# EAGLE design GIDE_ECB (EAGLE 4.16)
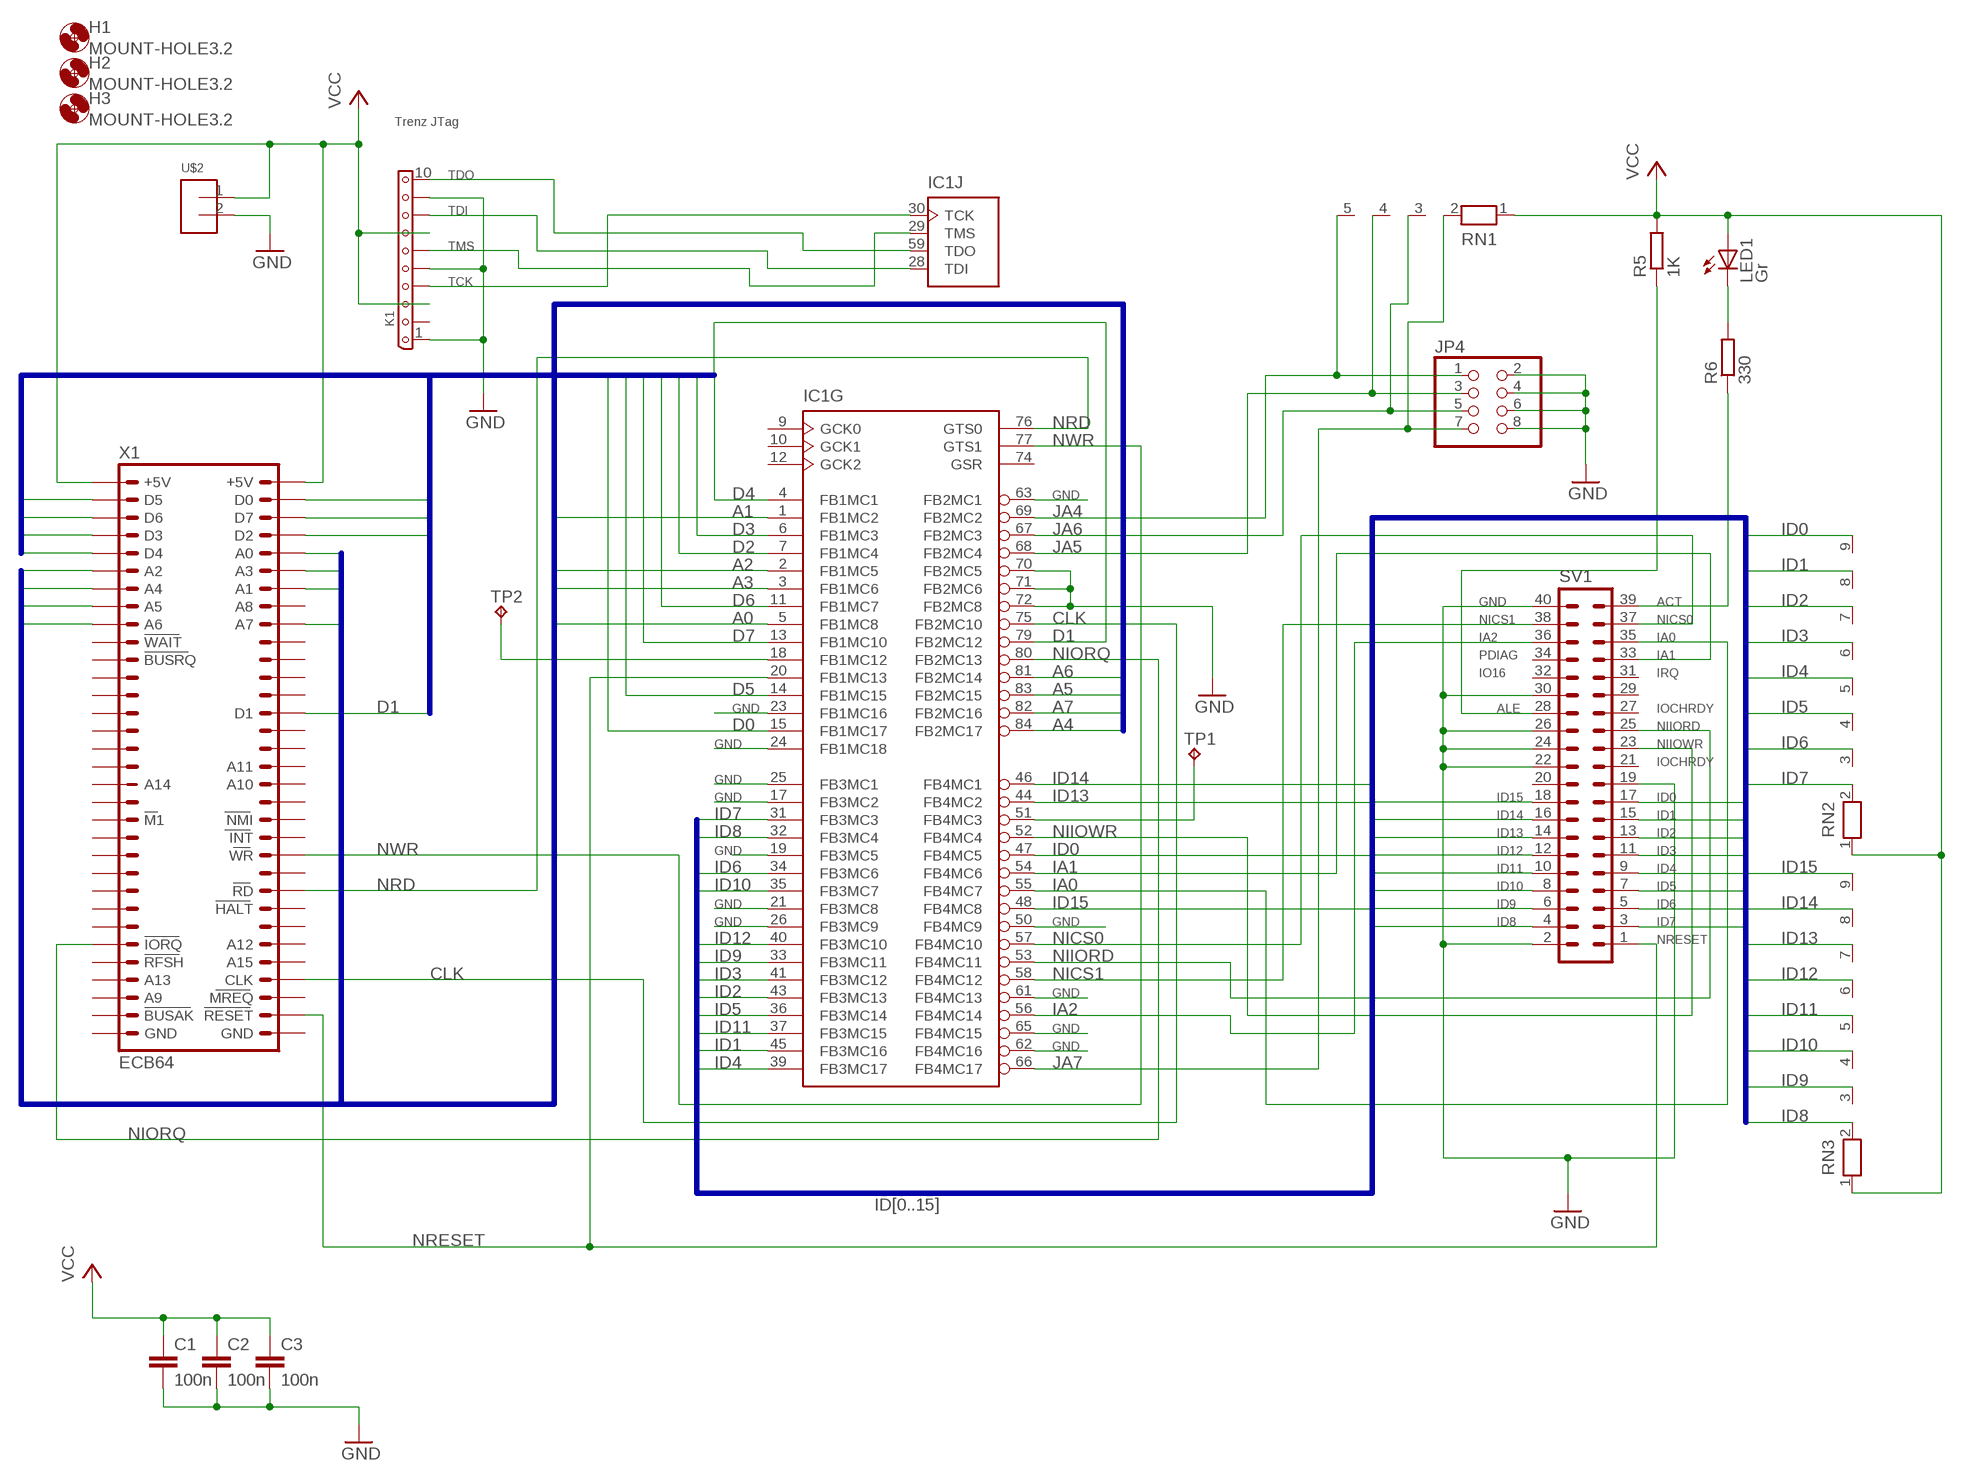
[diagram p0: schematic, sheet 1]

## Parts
C1  100n  C-EU025-024X044  [C025-024X044]
C2  100n  C-EU025-024X044  [C025-024X044]
C3  100n  C-EU025-024X044  [C025-024X044]
H1  MOUNT-HOLE3.2  [3,2]
H2  MOUNT-HOLE3.2  [3,2]
H3  MOUNT-HOLE3.2  [3,2]
IC1  XC9572PC84  [PLCC-S84]
JP4  PINHD-2X4  [2X04]
K1  PFOSTENSTECKER-10  [PFOSTENSTECKER-10]
LED1  Gr  LED3MM  [LED3MM]
R5  1K  R-EU_0207/10  [0207/10]
R6  330  R-EU_0204/7  [0204/7]
RN1  RN04  [RN-5]
RN2  RN08  [RN-9]
RN3  RN08  [RN-9]
SV1  ML40  [ML40]
TP1  TPPAD1-13  [P1-13]
TP2  TPPAD1-13  [P1-13]
U$2  PS25/2G  [PS25-2G]
X1  ECB64  [ML64ECB]

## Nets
A0: IC1.5(G:FB1MC8) X1.A0
A1: IC1.1(G:FB1MC2) X1.A1
A2: IC1.2(G:FB1MC5) X1.A2
A3: IC1.3(G:FB1MC6) X1.A3
A4: IC1.84(G:FB2MC17) X1.A4
A5: IC1.83(G:FB2MC15) X1.A5
A6: IC1.81(G:FB2MC14) X1.A6
A7: IC1.82(G:FB2MC16) X1.A7
ACT: R6.1 SV1.39
ALE: R5.1 SV1.28
CLK: IC1.75(G:FB2MC10) X1.CLK
D0: IC1.15(G:FB1MC17) X1.D0
D1: IC1.79(G:FB2MC12) X1.D1
D2: IC1.7(G:FB1MC4) X1.D2
D3: IC1.6(G:FB1MC3) X1.D3
D4: IC1.4(G:FB1MC1) X1.D4
D5: IC1.14(G:FB1MC15) X1.D5
D6: IC1.11(G:FB1MC7) X1.D6
D7: IC1.13(G:FB1MC10) X1.D7
GND: C1.2 C2.2 C3.2 IC1.17(G:FB3MC2) IC1.19(G:FB3MC5) IC1.21(G:FB3MC8) IC1.23(G:FB1MC16) IC1.24(G:FB1MC18) IC1.25(G:FB3MC1) IC1.26(G:FB3MC9) IC1.50(G:FB4MC9) IC1.61(G:FB4MC13) IC1.62(G:FB4MC16) IC1.63(G:FB2MC1) IC1.65(G:FB4MC15) IC1.70(G:FB2MC5) IC1.71(G:FB2MC6) IC1.72(G:FB2MC8) JP4.2 JP4.4 JP4.6 JP4.8 K1.1 K1.5 K1.9 SV1.2 SV1.19 SV1.22 SV1.24 SV1.26 SV1.30 SV1.40 U$2.2
IA0: IC1.55(G:FB4MC7) SV1.35
IA1: IC1.54(G:FB4MC6) SV1.33
IA2: IC1.56(G:FB4MC14) SV1.36
ID0: IC1.47(G:FB4MC5) RN2.9 SV1.17
ID1: IC1.45(G:FB3MC16) RN2.8 SV1.15
ID2: IC1.43(G:FB3MC13) RN2.7 SV1.13
ID3: IC1.41(G:FB3MC12) RN2.6 SV1.11
ID4: IC1.39(G:FB3MC17) RN2.5 SV1.9
ID5: IC1.36(G:FB3MC14) RN2.4 SV1.7
ID6: IC1.34(G:FB3MC6) RN2.3 SV1.5
ID7: IC1.31(G:FB3MC3) RN2.2 SV1.3
ID8: IC1.32(G:FB3MC4) RN3.2 SV1.4
ID9: IC1.33(G:FB3MC11) RN3.3 SV1.6
ID10: IC1.35(G:FB3MC7) RN3.4 SV1.8
ID11: IC1.37(G:FB3MC15) RN3.5 SV1.10
ID12: IC1.40(G:FB3MC10) RN3.6 SV1.12
ID13: IC1.44(G:FB4MC2) RN3.7 SV1.14
ID14: IC1.46(G:FB4MC1) RN3.8 SV1.16
ID15: IC1.48(G:FB4MC8) RN3.9 SV1.18
JA4: IC1.69(G:FB2MC2) JP4.1 RN1.5
JA5: IC1.68(G:FB2MC4) JP4.3 RN1.4
JA6: IC1.67(G:FB2MC3) JP4.5 RN1.3
JA7: IC1.66(G:FB4MC17) JP4.7 RN1.2
N$1: IC1.51(G:FB4MC3) TP1.1(TP)
N$2: IC1.18(G:FB1MC12) TP2.1(TP)
N$16: LED1.K(C) R6.2
NICS0: IC1.57(G:FB4MC10) SV1.37
NICS1: IC1.58(G:FB4MC12) SV1.38
NIIORD: IC1.53(G:FB4MC11) SV1.25
NIIOWR: IC1.52(G:FB4MC4) SV1.23
NIORQ: IC1.80(G:FB2MC13) X1.IORQ
NRD: IC1.76(G:GTS0) X1.RD
NRESET: IC1.20(G:FB1MC13) SV1.1 X1.RESET
NWR: IC1.77(G:GTS1) X1.WR
TCK: IC1.30(J:TCK) K1.4
TDI: IC1.28(J:TDI) K1.8
TDO: IC1.59(J:TDO) K1.10
TMS: IC1.29(J:TMS) K1.6
VCC: C1.1 C2.1 C3.1 K1.3 K1.7 LED1.A R5.2 RN1.1 RN2.1 RN3.1 U$2.1 X1.+5V X1.+5V@1(+5V)
Unconnected: IC1.9(G:GCK0) IC1.10(G:GCK1) IC1.12(G:GCK2) IC1.74(G:GSR) K1.2 SV1.20 SV1.21 SV1.27 SV1.29 SV1.31 SV1.32 SV1.34 X1.10C X1.11C X1.12A X1.12C X1.13A X1.13C X1.14A X1.15A X1.15C X1.16A X1.16C X1.17A X1.19A X1.19C X1.21A X1.22A X1.23A X1.23C X1.24A X1.25A X1.26A X1.26C X1.A8 X1.A9 X1.A10 X1.A11 X1.A12 X1.A13 X1.A14 X1.A15 X1.BUSAK X1.BUSRQ X1.HALT X1.INT X1.M1 X1.MREQ X1.NMI X1.RFSH X1.WAIT

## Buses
ID[0..15]
D[0..7]
A[0..7]

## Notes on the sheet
- Trenz JTag
- PDIAG
- IO16 | IRQ
- IOCHRDY
- IOCHRDY

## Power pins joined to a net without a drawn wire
GND: IC1.8(P:GND) IC1.16(P:GND) IC1.27(P:GND) IC1.42(P:GND) IC1.49(P:GND) IC1.60(P:GND) X1.GND X1.GND@1(GND)
VCC: IC1.22(P:VCC) IC1.38(P:VCC) IC1.64(P:VCC) IC1.73(P:VCC) IC1.78(P:VCC)

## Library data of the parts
C1-C3 = rcl:C-EU: CAPACITOR, European symbol
H1-H3 = holes:MOUNT-HOLE: MOUNTING HOLE with drill center marker
IC1 = XILINX:XC9572PC84
JP4 = pinhead:PINHD-2X4: PIN HEADER
K1 = ad:PFOSTENSTECKER-10
LED1 = led:LED: LED
R5 R6 = rcl:R-EU_: RESISTOR, European symbol
RN1 = resistor-net:RN04: RESISTOR NETWORK
RN2 RN3 = resistor-net:RN08: RESISTOR NETWORK
SV1 = con-harting-ml:ML40: HARTING
TP1 TP2 = testpad:TP
U$2 = ad:PS25/2G: Reichelt PS 25/2G
X1 = eigene:ECB64: CONNECTOR male, 64 pins, block, type C, rows AC, grid 5.08 mm

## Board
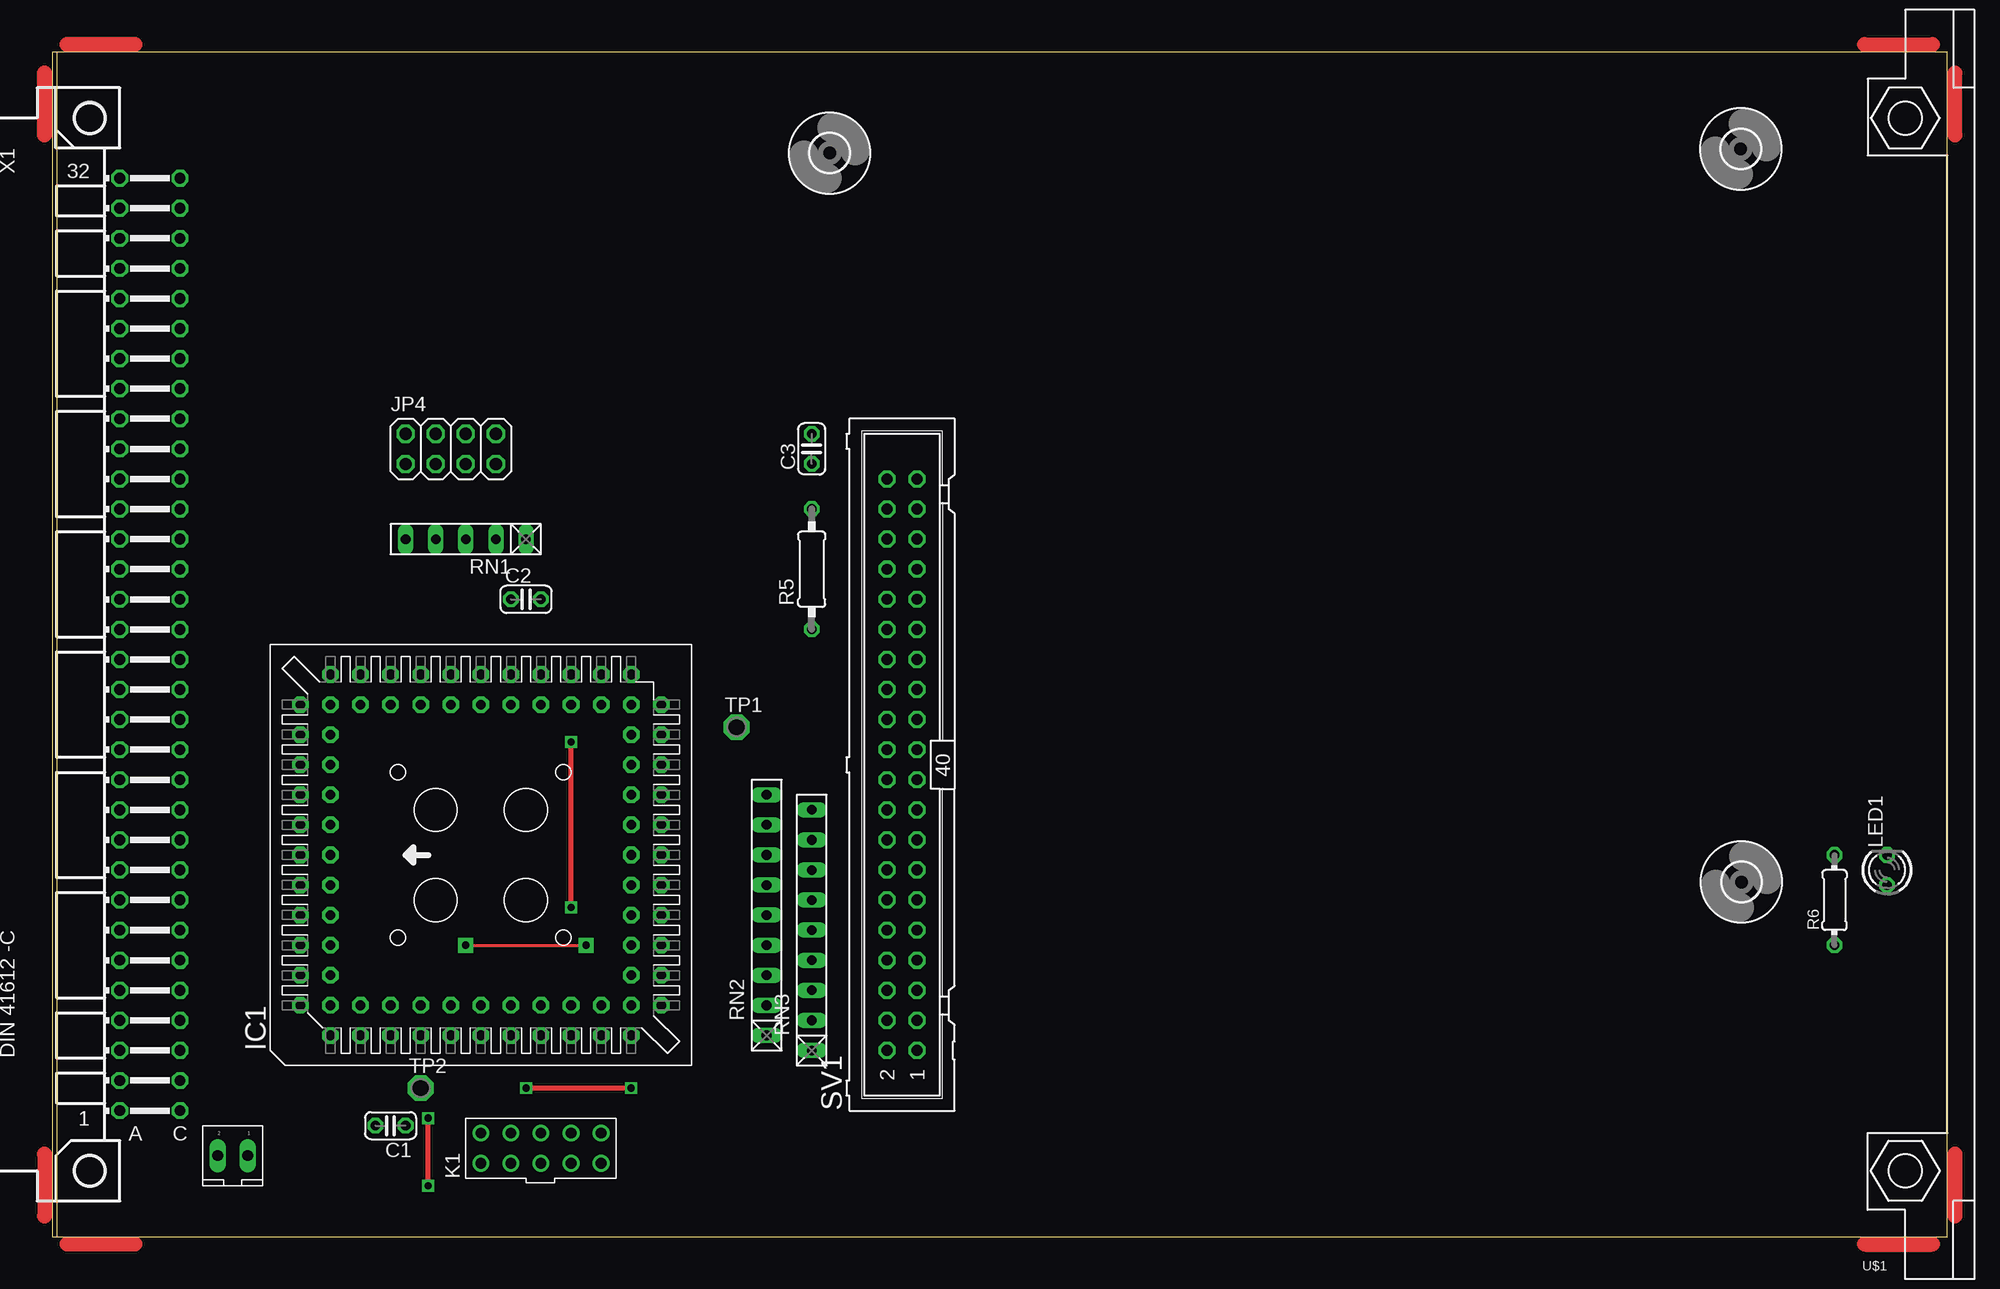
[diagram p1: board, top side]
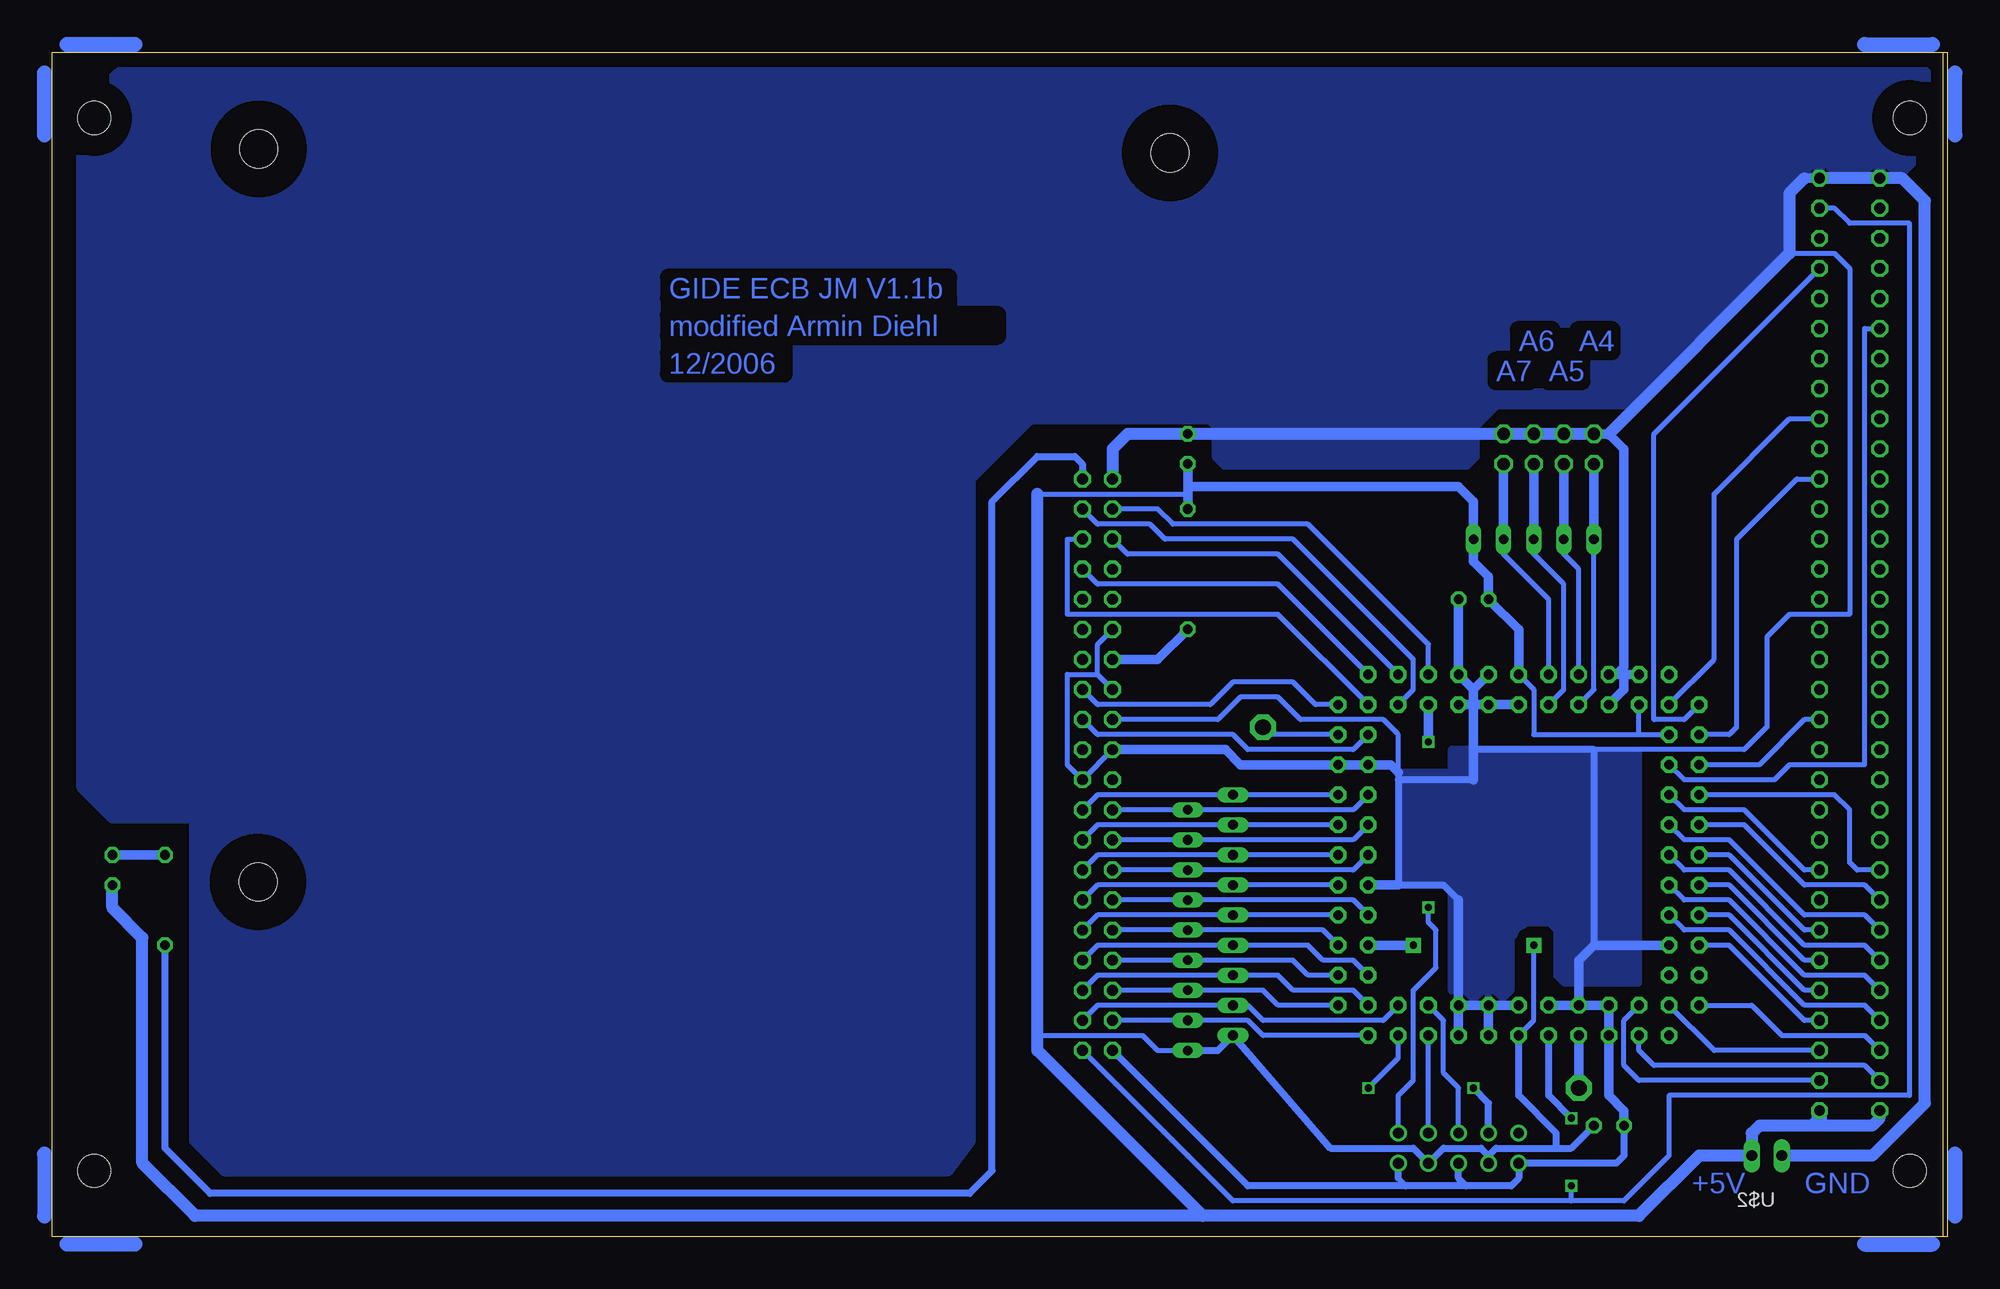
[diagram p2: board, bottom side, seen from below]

Size 160.02 x 100.03 mm. Coordinates in mm from the lower left corner, seen from the top.
Copper layers (1*16): Top 0.035mm / dielectric 1.5mm / Bottom 0.035mm
Design rules "olimex10mils": minimum track width 10mil, minimum drill 0.6mm, track to track 30mil, track to pad 10mil, pad to pad 10mil, via to via 10mil, smd to smd 10mil, copper to edge 40mil, drill to drill 10mil, minimum pad ring 10mil, minimum via ring 8mil, stop-mask expansion 0mil, vias tented up to drill 0mil, thermal gap 10mil

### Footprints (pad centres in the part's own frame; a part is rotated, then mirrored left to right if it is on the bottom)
C025-024X044 = drill 0.813 octagon: 1 -1.27,0; 2 1.27,0
3,2 = hole 3.2: 0,0
PLCC-S84 = drill 0.813 pad 1.397 octagon: 1 0,15.24; 2 0,12.7; 3 -2.54,15.24; 4 -2.54,12.7; 5 -5.08,15.24; 6 -5.08,12.7; 7 -7.62,15.24; 8 -7.62,12.7; 9 -10.16,15.24; 10 -10.16,12.7; 11 -12.7,15.24; 12 -15.24,12.7; 13 -12.7,12.7; 14 -15.24,10.16; 15 -12.7,10.16; 16 -15.24,7.62; 17 -12.7,7.62; 18 -15.24,5.08; 19 -12.7,5.08; 20 -15.24,2.54; 21 -12.7,2.54; 22 -15.24,0; 23 -12.7,0; 24 -15.24,-2.54; 25 -12.7,-2.54; 26 -15.24,-5.08; 27 -12.7,-5.08; 28 -15.24,-7.62; 29 -12.7,-7.62; 30 -15.24,-10.16; 31 -12.7,-10.16; 32 -15.24,-12.7; 33 -12.7,-15.24; 34 -12.7,-12.7; 35 -10.16,-15.24; 36 -10.16,-12.7; 37 -7.62,-15.24; 38 -7.62,-12.7; 39 -5.08,-15.24; 40 -5.08,-12.7; 41 -2.54,-15.24; 42 -2.54,-12.7; 43 0,-15.24; 44 0,-12.7; 45 2.54,-15.24; 46 2.54,-12.7; 47 5.08,-15.24; 48 5.08,-12.7; 49 7.62,-15.24; 50 7.62,-12.7; 51 10.16,-15.24; 52 10.16,-12.7; 53 12.7,-15.24; 54 15.24,-12.7; 55 12.7,-12.7; 56 15.24,-10.16; 57 12.7,-10.16; 58 15.24,-7.62; 59 12.7,-7.62; 60 15.24,-5.08; 61 12.7,-5.08; 62 15.24,-2.54; 63 12.7,-2.54; 64 15.24,0; 65 12.7,0; 66 15.24,2.54; 67 12.7,2.54; 68 15.24,5.08; 69 12.7,5.08; 70 15.24,7.62; 71 12.7,7.62; 72 15.24,10.16; 73 12.7,10.16; 74 15.24,12.7; 75 12.7,15.24; 76 12.7,12.7; 77 10.16,15.24; 78 10.16,12.7; 79 7.62,15.24; 80 7.62,12.7; 81 5.08,15.24; 82 5.08,12.7; 83 2.54,15.24; 84 2.54,12.7
2X04 = drill 1.016 octagon: 1 -3.81,-1.27; 2 -3.81,1.27; 3 -1.27,-1.27; 4 -1.27,1.27; 5 1.27,-1.27; 6 1.27,1.27; 7 3.81,-1.27; 8 3.81,1.27
PFOSTENSTECKER-10 = drill 0.9 round: 1 -1.27,5.08; 2 1.27,5.08; 3 -1.27,2.54; 4 1.27,2.54; 5 -1.27,0; 6 1.27,0; 7 -1.27,-2.54; 8 1.27,-2.54; 9 -1.27,-5.08; 10 1.27,-5.08
LED3MM = drill 0.813 octagon: A -1.27,0; K 1.27,0
0207/10 = drill 0.813 octagon: 1 -5.08,0; 2 5.08,0
0204/7 = drill 0.813 octagon: 1 -3.81,0; 2 3.81,0
RN-5 = drill 0.813 long: 1 -5.08,0; 2 -2.54,0; 3 0,0; 4 2.54,0; 5 5.08,0
RN-9 = drill 0.813 long: 1 -10.16,0; 2 -7.62,0; 3 -5.08,0; 4 -2.54,0; 5 0,0; 6 2.54,0; 7 5.08,0; 8 7.62,0; 9 10.16,0
ML40 = drill 0.914 octagon: 1 -24.13,-1.27; 2 -24.13,1.27; 3 -21.59,-1.27; 4 -21.59,1.27; 5 -19.05,-1.27; 6 -19.05,1.27; 7 -16.51,-1.27; 8 -16.51,1.27; 9 -13.97,-1.27; 10 -13.97,1.27; 11 -11.43,-1.27; 12 -11.43,1.27; 13 -8.89,-1.27; 14 -8.89,1.27; 15 -6.35,-1.27; 16 -6.35,1.27; 17 -3.81,-1.27; 18 -3.81,1.27; 19 -1.27,-1.27; 20 -1.27,1.27; 21 1.27,-1.27; 22 1.27,1.27; 23 3.81,-1.27; 24 3.81,1.27; 25 6.35,-1.27; 26 6.35,1.27; 27 8.89,-1.27; 28 8.89,1.27; 29 11.43,-1.27; 30 11.43,1.27; 31 13.97,-1.27; 32 13.97,1.27; 33 16.51,-1.27; 34 16.51,1.27; 35 19.05,-1.27; 36 19.05,1.27; 37 21.59,-1.27; 38 21.59,1.27; 39 24.13,-1.27; 40 24.13,1.27
P1-13 = drill 1.321 pad 2.159 octagon: 1 0,0
EK-FP = hole 2.794: 3.556,44.45; 3.556,-44.45
PS25-2G = drill 0.9 long: 1 -2.54,0; 2 0,0
ML64ECB = drill 0.914 octagon: 10C 16.51,17.78; 11C 13.97,17.78; 12A 11.43,12.7; 12C 11.43,17.78; 13A 8.89,12.7; 13C 8.89,17.78; 14A 6.35,12.7; 15A 3.81,12.7; 15C 3.81,17.78; 16A 1.27,12.7; 16C 1.27,17.78; 17A -1.27,12.7; 19A -6.35,12.7; 19C -6.35,17.78; 21A -11.43,12.7; 22A -13.97,12.7; 23A -16.51,12.7; 23C -16.51,17.78; 24A -19.05,12.7; 25A -21.59,12.7; 26A -24.13,12.7; 26C -24.13,17.78; +5V 39.37,12.7; +5V@1 39.37,17.78; A0 29.21,17.78; A1 24.13,17.78; A2 26.67,12.7; A3 26.67,17.78; A4 24.13,12.7; A5 21.59,12.7; A6 19.05,12.7; A7 19.05,17.78; A8 21.59,17.78; A9 -34.29,12.7; A10 -3.81,17.78; A11 -1.27,17.78; A12 -26.67,17.78; A13 -31.75,12.7; A14 -3.81,12.7; A15 -29.21,17.78; BUSAK -36.83,12.7; BUSRQ 13.97,12.7; CLK -31.75,17.78; D0 36.83,17.78; D1 6.35,17.78; D2 31.75,17.78; D3 31.75,12.7; D4 29.21,12.7; D5 36.83,12.7; D6 34.29,12.7; D7 34.29,17.78; GND -39.37,12.7; GND@1 -39.37,17.78; HALT -21.59,17.78; INT -11.43,17.78; IORQ -26.67,12.7; M1 -8.89,12.7; MREQ -34.29,17.78; NMI -8.89,17.78; RD -19.05,17.78; RESET -36.83,17.78; RFSH -29.21,12.7; WAIT 16.51,12.7; WR -13.97,17.78 | hole 2.794: -44.45,10.16; 44.45,10.16

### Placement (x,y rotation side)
C1  28.58,9.37 180 top
C2  40.01,53.82 0 top
C3  64.14,66.52 90 top
H1  142.64,29.95 0 top
H2  142.58,91.85 0 top
H3  65.65,91.51 0 top
IC1  36.2,32.23 90 top
JP4  33.66,66.52 0 top
K1  41.28,7.47 90 top
LED1  154.94,30.96 90 top
R5  64.14,56.36 90 top
R6  150.5,28.42 90 top
RN1  34.93,58.9 180 top
RN2  60.33,27.15 90 top
RN3  64.14,25.88 90 top
SV1  71.76,39.85 90 top
TP1  57.79,43.03 0 top
TP2  31.12,12.55 0 top
U$1  [EK-FP]  160.02,50.01 180 top
U$2  13.97,6.83 180 top
X1  -6.98,50.01 270 top

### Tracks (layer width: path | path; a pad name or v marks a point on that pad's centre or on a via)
A0
  Bottom 0.406: IC1.5 18.42,27.15 12.07,20.8 X1.A0
A1
  Bottom 0.406: IC1.1 18.42,32.23 12.07,25.88 X1.A1
A2
  Bottom 0.406: IC1.2 22.23,30.96 18.42,30.96 12.07,24.61 6.99,24.61 X1.A2
A3
  Bottom 0.406: IC1.3 18.42,29.69 12.07,23.34 X1.A3
A4
  Bottom 0.406: IC1.84 22.23,33.5 18.42,33.5 12.07,27.15 6.99,27.15 X1.A4
A5
  Bottom 0.406: IC1.83 17.15,34.77 12.07,29.69 6.99,29.69 X1.A5
A6
  Bottom 0.406: X1.A6 7.62,30.96 8.26,31.6 8.26,36.04 9.53,37.31 IC1.81
A7
  Bottom 0.406: IC1.82 22.23,36.04 17.15,36.04 12.07,30.96 X1.A7
ACT
  Bottom 0.61: R6.1 150.5,7.47 146.69,3.66 82.55,3.66 80.65,5.56 80.65,62.08 76.84,65.89 73.66,65.89 73.03,65.25 SV1.39
ALE
  Bottom 0.813: R5.1 66.68,48.74 SV1.28
CLK
  Bottom 0.406: IC1.75 22.23,43.66 24.77,43.66 24.77,67.79 X1.CLK
D0
  Bottom 0.406: IC1.15 27.31,18.26 27.31,14.45 26.04,13.18 X1.D0
D1
  Bottom 0.406: IC1.79 15.88,39.85 12.07,43.66 X1.D1
D2
  Bottom 0.406: IC1.7 18.42,24.61 12.07,18.26 X1.D2
D3
  Bottom 0.406: IC1.6 22.23,25.88 18.42,25.88 12.07,19.53 6.99,19.53 X1.D3
D4
  Bottom 0.406: IC1.4 22.23,28.42 18.42,28.42 12.07,22.07 6.99,22.07 X1.D4
D5
  Bottom 0.406: IC1.14 26.04,15.72 24.77,14.45 6.99,14.45 X1.D5
D6
  Bottom 0.406: X1.D6 6.99,16.99 13.97,16.99 16.51,19.53 IC1.11
D7
  Bottom 0.406: IC1.13 19.69,15.72 X1.D7
GND
  Bottom 0.406: SV1.30 71.76,50.01 71.76,47.47 | 71.76,47.47 SV1.26 | SV1.22 SV1.19 74.3,39.85 74.3,47.47 71.76,47.47 | 46.36,38.58 46.36,39.22 46.36,42.39 47.63,43.66 54.61,43.66 56.52,45.57 59.69,45.57 61.6,43.66 SV1.24 | 13.34,83.03 9.53,83.03 8.26,81.76 8.26,52.55 13.34,52.55 15.24,50.65 15.24,43.03 17.15,41.12 29.85,41.12 | 45.72,4.29 46.36,4.93
  Bottom 0.61: SV1.2 59.06,4.29 45.72,4.29 40.64,4.29 | 40.01,41.12 29.85,41.12 29.85,24.61 | 40.01,38.58 46.36,38.58 46.36,29.69 42.55,29.69 41.28,28.42 | C1.2 27.31,6.83 27.94,6.2 K1.1 36.2,4.93 36.83,4.29 40.64,4.29 | 40.64,4.29 41.28,4.93 K1.5 | 46.36,4.93 K1.9
  Bottom 0.813: SV1.22 60.96,41.12 59.69,39.85 IC1.49 IC1.50 46.99,39.85 46.36,39.22 | IC1.8 29.85,24.61 31.12,23.34 IC1.19 | 46.36,29.69 IC1.42 | C2.2 IC1.60 40.01,46.2 | X1.GND@1 12.07,89.38 | JP4.2 28.58,67.79 27.31,66.52 27.31,48.11 27.94,47.47 IC1.70 27.31,47.47 | C1.2 27.31,10.64 28.58,11.91 IC1.16 IC1.17 IC1.19 | 41.28,28.42 IC1.27 | IC1.19 IC1.21 | IC1.27 IC1.26 | IC1.27 IC1.25 | IC1.25 IC1.24 | IC1.71 27.31,46.2 27.31,47.47 | 27.31,47.47 IC1.72 | 40.01,44.93 40.01,41.12 40.01,38.58 | 40.01,44.93 40.01,46.2 | 40.01,46.2 IC1.62 | IC1.65 IC1.63 40.01,44.93 | 40.01,44.93 IC1.61 | IC1.25 IC1.23
  Bottom 1.016: JP4.2 JP4.4 JP4.6 JP4.8 C3.2 69.22,67.79 70.49,66.52 SV1.40 | X1.GND@1 X1.GND 3.81,89.38 1.91,87.48 1.91,11.28 6.35,6.83 U$2.2 | 28.58,67.79 13.34,83.03 13.34,88.11 12.07,89.38
  pour Bottom: 26.04,41.12 41.91,41.12 41.91,39.22 46.36,39.22 46.36,29.69 42.55,29.69 41.91,29.06 41.91,20.8 41.28,20.17 37.47,20.17 36.83,20.8 36.83,25.25 35.56,26.52 33.66,26.52 33.02,25.88 33.02,22.07 32.39,21.44 26.04,21.44
  pour Bottom: 1.91,91.92 3.81,90.02 11.43,90.02 13.34,88.11 13.34,83.67 13.97,83.03 14.61,83.03 27.31,70.33 38.1,70.33 40.01,68.43 40.01,65.89 40.64,65.25 60.96,65.25 61.6,65.89 61.6,68.43 62.23,69.06 77.47,69.06 82.55,63.98 82.55,8.1 84.46,5.56 145.42,5.56 147.96,8.1 147.96,35.41 154.94,35.41 157.48,37.95 157.48,95.1 154.31,98.27 1.91,98.27
IA0
  Bottom 0.406: IC1.55 56.52,52.55 74.3,52.55 74.3,58.9 SV1.35
IA1
  Bottom 0.406: IC1.54 56.52,55.09 71.76,55.09 SV1.33
IA2
  Bottom 0.406: IC1.56 56.52,57.63 69.22,57.63 SV1.36
ID0
  Bottom 0.406: IC1.47 RN2.9 71.76,37.31 SV1.17
ID1
  Bottom 0.406: IC1.45 RN2.8 71.76,34.77 SV1.15
ID2
  Bottom 0.406: IC1.43 RN2.7 71.76,32.23 SV1.13
ID3
  Bottom 0.406: IC1.41 RN2.6 71.76,29.69 SV1.11
ID4
  Bottom 0.406: IC1.39 RN2.5 71.76,27.15 SV1.9
ID5
  Bottom 0.406: SV1.7 71.76,24.61 RN2.4 53.98,24.61 52.71,23.34 50.17,23.34 IC1.36
ID6
  Bottom 0.406: SV1.5 71.76,22.07 RN2.3 56.52,22.07 55.25,20.8 50.17,20.8 IC1.34
ID7
  Bottom 0.406: SV1.3 71.76,19.53 RN2.2 59.06,19.53 57.79,18.26 47.63,18.26 IC1.31
ID8
  Bottom 0.406: SV1.4 RN3.2 59.06,18.26 57.79,16.99 IC1.32
ID9
  Bottom 0.406: SV1.6 RN3.3 57.79,20.8 56.52,19.53 IC1.33
ID10
  Bottom 0.406: SV1.8 RN3.4 55.25,23.34 53.98,22.07 IC1.35
ID11
  Bottom 0.406: SV1.10 RN3.5 52.71,25.88 IC1.37
ID12
  Bottom 0.406: SV1.12 RN3.6 50.17,28.42 IC1.40
ID13
  Bottom 0.406: SV1.14 RN3.7 50.17,30.96 IC1.44
ID14
  Bottom 0.406: SV1.16 RN3.8 50.17,33.5 IC1.46
ID15
  Bottom 0.406: SV1.18 RN3.9 50.17,36.04 IC1.48
JA4
  Bottom 0.406: IC1.69 29.85,46.2 RN1.5
  Bottom 0.813: RN1.5 JP4.1
JA5
  Bottom 0.406: IC1.68 31.12,56.36 32.39,57.63 RN1.4
  Bottom 0.813: RN1.4 JP4.3
JA6
  Bottom 0.406: IC1.67 32.39,46.2 32.39,55.09 34.93,57.63 RN1.3
  Bottom 0.813: RN1.3 JP4.5
JA7
  Bottom 0.406: IC1.66 33.66,53.82 37.47,57.63 RN1.2
  Bottom 0.813: RN1.2 JP4.7
N$1
  Bottom 0.406: IC1.51 57.15,42.39 TP1.1
N$2
  Bottom 0.813: TP2.1 IC1.18
N$16
  Bottom 0.813: R6.2 LED1.K
NICS0
  Bottom 0.406: IC1.57 45.09,46.2 45.09,48.74 55.25,58.9 66.04,58.9 67.31,60.17 71.76,60.17 SV1.37
NICS1
  Bottom 0.406: IC1.58 43.82,50.01 53.98,60.17 65.41,60.17 66.68,61.44 SV1.38
NIIORD
  Bottom 0.406: SV1.25 71.76,44.93 62.23,44.93 60.33,46.84 55.25,46.84 53.34,44.93 IC1.53
NIIOWR
  Bottom 0.406: IC1.52 50.17,41.12 59.06,41.12 60.33,42.39 71.76,42.39 SV1.23
NIORQ
  Bottom 0.406: IC1.80 22.23,38.58 14.61,38.58 13.34,39.85 6.99,39.85 6.99,76.68 X1.IORQ
NRD
  Bottom 0.406: X1.RD 13.34,69.06 19.69,62.71 19.69,48.74 IC1.76
NRESET  (via drill 0.6)
  Top 0.406: v31.75,4.29 v31.75,10.01
  Bottom 0.406: X1.RESET 9.53,86.84 8.26,85.57 3.18,85.57 3.18,11.91 23.5,11.91 23.5,6.83 27.31,3.02 31.75,3.02 | SV1.1 60.33,3.02 31.75,3.02 | 31.75,3.02 v31.75,4.29
  Bottom 0.61: IC1.20 33.66,11.91 v31.75,10.01
NWR
  Bottom 0.406: X1.WR 12.7,63.98 17.78,58.9 17.78,43.03 18.42,42.39 IC1.77
TCK  (via drill 0.6)
  Top 0.406: v40.01,12.55 v48.9,12.55
  Bottom 0.406: IC1.30 46.36,15.09 v48.9,12.55
  Bottom 0.61: v40.01,12.55 38.74,11.28 K1.4
TDI
  Bottom 0.406: K1.8 IC1.28
TDO  (via drill 0.6)
  Top 0.406: v43.82,27.79 v43.82,41.76
  Bottom 0.406: v43.82,27.79 43.82,26.52 43.18,25.88 43.18,22.71 45.09,20.8 45.09,13.18 46.36,11.91 K1.10
  Bottom 0.813: v43.82,41.76 IC1.59
TMS
  Bottom 0.406: K1.6 41.28,12.55 42.55,13.82 42.55,18.26 IC1.29
VCC  (via drill 0.6 pad 1.27)
  Top 0.254: v34.93,24.61 v45.09,24.61
  Bottom 0.406: 26.04,42.39 IC1.78 | 26.04,42.39 IC1.73 | 26.04,42.39 34.93,42.39 34.93,46.2 IC1.64 | 76.84,62.71 64.14,62.71 | v34.93,24.61 34.93,18.26 IC1.22 | 76.84,16.99 67.95,16.99 66.68,15.72 RN3.1
  Bottom 0.61: 38.74,6.83 39.37,7.47 42.55,7.47 K1.7 45.09,7.47 52.07,7.47 RN2.1 61.6,15.72 RN3.1 | 38.74,6.83 K1.3 | 38.74,6.83 38.1,7.47 33.02,7.47 | 33.02,7.47 31.75,7.47 C1.1 | IC1.22 36.2,11.91 33.02,8.74 33.02,7.47
  Bottom 0.813: IC1.64 36.2,51.28 C2.1 38.74,55.73 40.01,57 RN1.1 40.01,62.08 41.28,63.35 64.14,63.35 | R5.2 64.14,62.71 64.14,63.35 | 64.14,63.35 C3.1 | v45.09,24.61 IC1.38
  Bottom 1.016: 62.87,1.75 26.04,1.75 20.96,6.83 U$2.1 16.51,8.74 15.88,9.37 11.43,9.37 | 62.87,1.75 76.84,15.72 76.84,16.99 76.84,62.71 | 62.87,1.75 147.96,1.75 152.4,6.2 152.4,25.25 154.94,27.79 LED1.A | X1.+5V 5.72,10.01 6.35,9.37 11.43,9.37 | 11.43,9.37 10.8,10.01
  Bottom 1.27: 10.8,10.01 X1.+5V@1

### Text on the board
Bottom: GIDE ECB JM V1.1b | modified Armin Diehl | A4 | A6 | 12/2006 | A5 | A7 | GND | +5V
